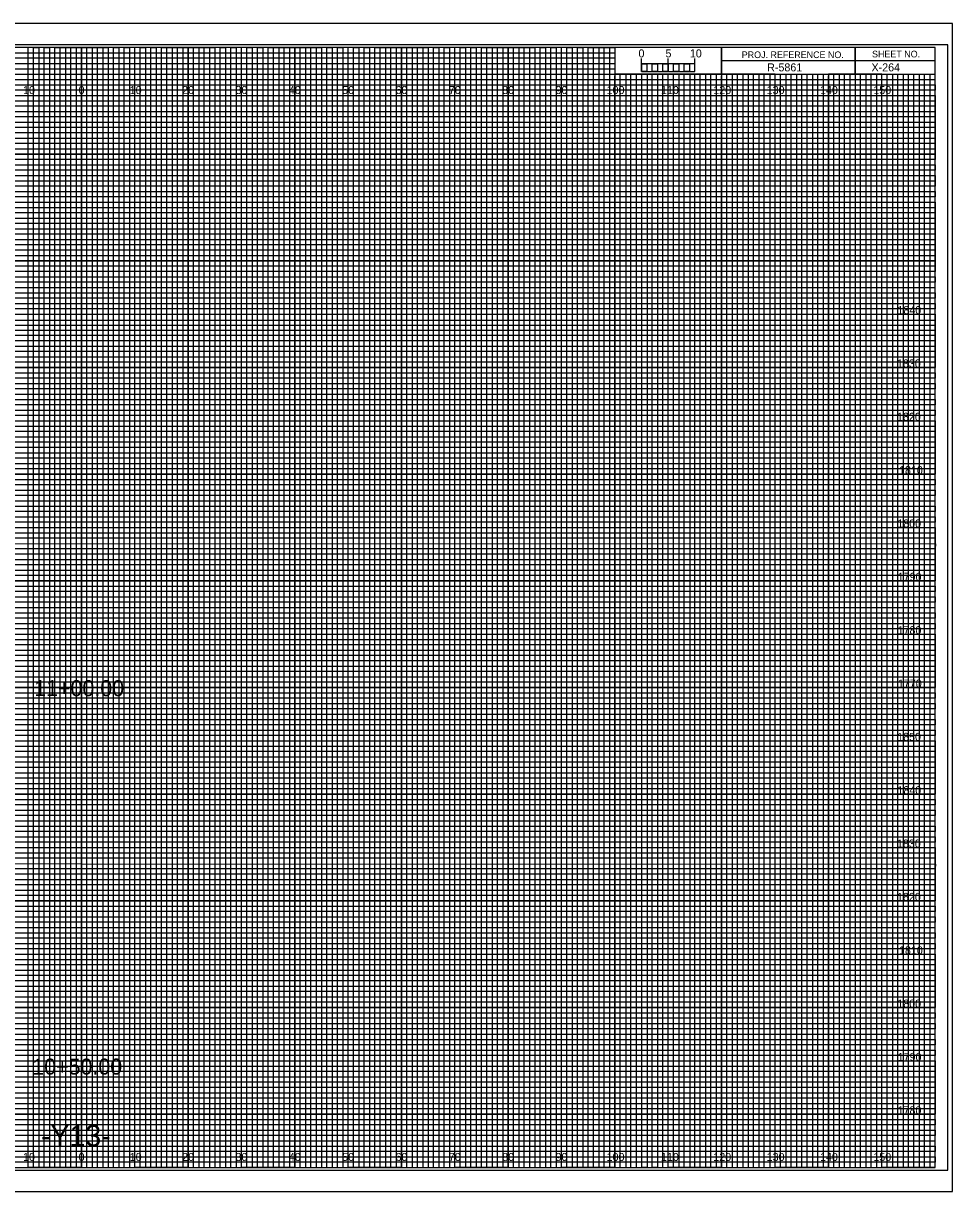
# Model space of a CAD drawing. Extents: x -13 to 323, y -5 to 654.
# Drawn here: x 149.1 to 323.3, y -4.5 to 214.5 of the extents above; entities that cross this region are included whole.
import ezdxf

# ---------------------------------------------------------------- set-up
doc = ezdxf.new("R2010")
doc.units = 0
for name, color, linetype in [('Prop Horizontal Alignment', 7, 'Continuous'), ('Prop XS Alignment Label', 7, 'Continuous'), ('Prop XS Bar Scale Labels', 7, 'Continuous'), ('Prop XS DDE', 7, 'Continuous'), ('Prop XS Earthwork Shape', 7, 'Continuous'), ('Prop XS Project Number', 7, 'Continuous'), ('Prop XS Sheet Number', 7, 'Continuous'), ('Raster_Level_0', 7, 'Continuous'), ('Scratch_Level_3', 7, 'Continuous'), ('Sheet Cross Section CELL', 7, 'Continuous'), ('Sheet Cross Section Grid Minor 1 CELL', 7, 'Continuous'), ('Sheet Cross Section Grid Minor 2 CELL', 7, 'Continuous'), ('Sheet Cross Section Scale CELL', 7, 'Continuous'), ('Sheet Cutting Line CELL', 7, 'Continuous'), ('Sheet DOT Grid CELL', 7, 'Continuous'), ('Sheet Plot Border Inside CELL', 7, 'Continuous'), ('Sheet Plot Border Outside CELL', 7, 'Continuous')]:
    doc.layers.add(name, color=color, linetype=linetype)

msp = doc.modelspace()

# ---------------------------------------------------------------- linework, layer by layer
at = {"layer": 'Prop XS DDE'}
for points in [[(145, 0), (155, 0), (155, 210), (165, 210), (165, 0), (175, 0), (175, 210), (185, 210), (185, 0), (195, 0), (195, 210), (205, 210), (205, 0), (215, 0), (215, 210), (225, 210), (225, 0), (235, 0), (235, 210), (245, 210), (245, 0), (255, 0), (255, 210), (259.93, 210), (260, 210), (260, 205), (264.99, 205), (264.99, 0), (275, 0), (275, 205), (285, 205), (285, 0), (295, 0), (295, 205), (305, 205), (305, 0), (315, 0), (315, 205)], [(0, 205), (275, 205)], [(0, 185), (320, 185), (320, 195), (0, 195)], [(0, 165), (320, 165), (320, 175), (0, 175)], [(0, 145), (320, 145), (320, 155), (0, 155)], [(0, 125), (320, 125), (320, 135), (0, 135)], [(0, 105), (320, 105), (320, 115), (0, 115)], [(0, 85), (320, 85), (320, 95), (0, 95)], [(0, 65), (320, 65), (320, 75), (0, 75)], [(0, 45), (320, 45), (320, 55), (0, 55)], [(0, 25), (320, 25), (320, 35), (0, 35)], [(0, 5), (320, 5), (320, 15), (0, 15)]]:
    msp.add_lwpolyline(points, dxfattribs=at)
at = {"layer": 'Prop XS Earthwork Shape'}
for p, q in [((150, 210), (140, 210)), ((150, 0), (150, 210)), ((170, 210), (160, 210)), ((160, 210), (160, 0)), ((170, 0), (170, 210)), ((190, 210), (180, 210)), ((180, 210), (180, 0)), ((190, 0), (190, 210)), ((210, 210), (200, 210)), ((200, 210), (200, 0)), ((210, 0), (210, 210)), ((230, 210), (220, 210)), ((220, 210), (220, 0)), ((230, 0), (230, 210)), ((250, 210), (240, 210)), ((240, 210), (240, 0)), ((250, 0), (250, 210)), ((260, 210), (260, 0)), ((270, 0), (270, 205)), ((290, 205), (280, 205)), ((280, 205), (280, 0)), ((290, 0), (290, 205)), ((310, 205), (300, 205)), ((300, 205), (300, 0)), ((310, 0), (310, 205)), ((160, 0), (150, 0)), ((180, 0), (170, 0)), ((200, 0), (190, 0)), ((220, 0), (210, 0)), ((240, 0), (230, 0)), ((260, 0), (250, 0)), ((280, 0), (270, 0)), ((300, 0), (290, 0)), ((320, 0), (310, 0)), ((320, 0), (320, 0))]:
    msp.add_line(p, q, dxfattribs=at)
for points in [[(0, 200), (320, 200), (320, 190), (0, 190)], [(0, 180), (320, 180), (320, 170), (0, 170)], [(0, 160), (320, 160), (320, 150), (0, 150)], [(0, 140), (320, 140), (320, 130), (0, 130)], [(0, 120), (320, 120), (320, 110), (0, 110)], [(0, 100), (320, 100), (320, 90), (0, 90)], [(0, 80), (320, 80), (320, 70), (0, 70)], [(0, 60), (320, 60), (320, 50), (0, 50)], [(0, 40), (320, 40), (320, 30), (0, 30)], [(0, 20), (320, 20), (320, 10), (0, 10)]]:
    msp.add_lwpolyline(points, dxfattribs=at)
at = {"layer": 'Sheet Cross Section CELL'}
for p, q in [((305, 210), (305, 205)), ((305, 205), (305, 210)), ((280, 207.5), (280, 205)), ((320, 207.49), (280, 207.49)), ((280, 205), (320, 205))]:
    msp.add_line(p, q, dxfattribs=at)
for points in [[(320, 210), (0, 210), (0, 0), (320, 0)], [(280, 210), (260, 210), (260, 205.03), (280, 205.03)], [(320, 210), (280, 210), (280, 205), (320, 205)]]:
    msp.add_lwpolyline(points, close=True, dxfattribs=at)
at = {"layer": 'Sheet Cross Section Grid Minor 1 CELL'}
for p, q in [((0, 209), (260, 209)), ((260, 209), (260, 207.98)), ((260, 207.98), (0, 207.98)), ((0, 207), (260, 207)), ((260, 205.89), (0, 205.89)), ((260, 207), (260, 205.89)), ((0, 204), (320, 204))]:
    msp.add_line(p, q, dxfattribs=at)
for points in [[(0, 203), (270, 203), (320, 203), (320, 202), (0, 202)], [(0, 201), (320, 201), (320, 199), (0, 199)], [(0, 198), (320, 198), (320, 197), (0, 196.98)], [(0, 196), (320, 196), (320, 194), (0, 194)], [(0, 193), (320, 193), (320, 192), (0, 192)], [(0, 191), (320, 191), (320, 189), (0, 189)], [(0, 188), (320, 188), (320, 187), (0, 187)], [(0, 186), (320, 186), (320, 184), (0, 184)], [(0, 183), (320, 183), (320, 182), (0, 182)], [(0, 181), (320, 181), (320, 179), (0, 179)], [(0, 178), (320, 178), (320, 177), (0, 177)], [(0, 176), (320, 176), (320, 173.95), (320, 173), (320, 172), (0, 172)], [(0, 174), (320, 174), (320, 173), (0, 173)], [(0, 171), (320, 171), (320, 169), (0, 169.03)], [(0, 169.03), (320, 169), (320, 168), (0, 168)], [(0, 167), (320, 167), (320, 166), (0, 166)], [(0, 164), (320, 164), (320, 163), (0, 163)], [(0, 162), (320, 162), (320, 161), (0, 161)], [(-0.07, 158.89), (320, 158.89), (320, 157.88), (-0.07, 157.88)], [(0, 157), (320, 157), (320, 156), (0, 156)], [(0, 154), (320, 154), (320, 153), (0, 153)], [(0, 152), (320, 152), (320, 151), (0, 151)], [(0, 149), (320, 149), (320, 148), (0, 148)], [(0, 147), (320, 147), (320, 146), (0, 146)], [(0, 144), (320, 144), (320, 143), (0, 143)], [(0, 142), (320, 142), (320, 141), (0, 141)], [(0, 139), (320, 139), (319.99, 137.98), (0, 138)], [(0, 137), (320, 137), (320, 136), (0, 136)], [(0, 134), (320, 134), (320, 133), (0, 133)], [(0, 132), (320, 132), (320, 131), (0, 131)], [(0, 129), (320, 129), (320, 128), (0, 128)], [(0, 127), (320, 127), (320, 126), (0, 126)], [(0, 124), (320, 124), (320, 123), (0, 123)], [(0, 122), (320, 122), (320, 121), (0, 121)], [(0, 119), (320, 119), (320, 118), (0, 118)], [(0, 116.99), (320.07, 116.91), (320, 116), (0, 116)], [(0, 114), (320, 114), (320, 113), (0, 113)], [(0, 112), (320, 112), (320, 111), (0, 111)], [(0, 109), (320, 109), (320, 108), (0, 108)], [(0, 107), (320, 107), (320, 106), (0, 106)], [(0, 104), (320, 104), (320, 103), (0, 103)], [(0, 102), (320, 102), (320, 101), (0, 101)], [(0, 99), (320, 99), (320, 98), (0, 98)], [(0, 97), (320, 97), (320, 96), (0, 96)], [(0, 94), (320, 94), (320, 93), (0, 93)], [(0, 92), (320, 92), (320, 91), (0, 91)], [(0, 89), (320, 89), (320, 88), (0, 88)], [(0, 87), (320, 87), (320, 86), (0, 86)], [(0, 84), (320, 84), (320, 83), (0, 83)], [(0, 82), (320, 82), (320, 81), (0, 81)], [(0, 79), (320, 79), (319.99, 77.98), (0, 78)], [(0, 77), (320, 77), (320, 76), (0, 76)], [(0, 74), (320, 74), (320, 73), (0, 73)], [(0, 72), (320, 72), (320, 71), (0, 71)], [(0, 69), (320, 69), (320, 68), (0, 68)], [(0, 67), (320, 67), (320, 66), (0, 66)], [(0, 64), (320, 64), (320, 63), (0, 63)], [(0, 62), (320, 62), (320, 61), (0, 61)], [(0, 59), (320, 59), (320, 58), (0, 58)], [(0, 56.99), (320.07, 56.91), (320, 56), (0, 56)], [(0, 54), (320, 54), (320, 53), (0, 53)], [(0, 52), (320, 52), (320, 51), (0, 51)], [(0, 49), (320, 49), (320, 48), (0, 48)], [(0, 47), (320, 47), (320, 46), (0, 46)], [(0, 44), (320, 44), (320, 43), (0, 43)], [(0, 42), (320, 42), (320, 41), (0, 41)], [(0, 39), (320, 39), (320, 38), (0, 38)], [(0, 37), (320, 37), (320, 36), (0, 36)], [(0, 34), (320, 34), (320, 33), (0, 33)], [(0, 32), (320, 32), (320, 31), (0, 31)], [(0, 29), (320, 29), (320, 28), (0, 28)], [(0, 27), (320, 27), (320, 26), (0, 26)], [(0, 24), (320, 24), (320, 23), (0, 23)], [(0, 22), (320, 22), (320, 21), (0, 21)], [(0, 19), (320, 19), (320, 18), (0, 18)], [(0, 17), (320, 17), (320, 16), (0, 16)], [(0, 14), (320, 14), (320, 13), (0, 13)], [(0, 12), (320, 12), (320, 11), (0, 11)], [(0, 9), (320, 9), (320, 8), (0, 8)], [(0, 7), (320, 7), (320, 6), (0, 6)], [(0, 4), (320, 4), (320, 3), (0, 3)], [(0, 2), (320, 2), (320, 1), (0, 1)]]:
    msp.add_lwpolyline(points, dxfattribs=at)
at = {"layer": 'Sheet Cross Section Grid Minor 2 CELL'}
for p, q in [((267, 205), (266.01, 205)), ((266.01, 205), (266.01, 0)), ((267, 0), (267, 205)), ((269, 205), (268, 205)), ((268, 205), (268, 0)), ((269, 0), (269, 205)), ((266.01, 0), (265, 0)), ((268, 0), (267, 0))]:
    msp.add_line(p, q, dxfattribs=at)
for points in [[(150, 0), (151, 0), (151, 210), (152, 210), (152, 0)], [(152, 0), (153, 0), (153, 210), (154, 210), (154, 0)], [(155, 0), (156, 0), (156, 210), (157, 210), (157, 0)], [(157, 0), (158, 0), (158, 210), (159, 210), (159, 0)], [(160, 0), (161, 0), (161, 210), (162, 210), (162, 0)], [(162, 0), (163, 0), (163, 210), (164, 210), (164, 0)], [(165, 0), (166, 0), (166, 210), (167, 210), (167, 0)], [(167, 0), (168, 0), (168, 210), (169, 210), (169, 0)], [(170, 0), (171, 0), (171, 210), (172, 210), (172, 0)], [(172, 0), (173, 0), (173, 210), (174, 210), (174, 0)], [(175, 0), (176, 0), (176, 210), (177, 210), (177, 0)], [(177, 0), (178, 0), (178, 210), (179, 210), (179, 0)], [(180, 0), (181, 0), (181, 210), (182, 210), (182, 0)], [(182, 0), (183, 0), (183, 210), (184, 210), (184, 0)], [(185, 0), (186, 0), (186, 210), (187, 210), (187, 0)], [(187, 0), (188, 0), (188, 210), (189, 210), (189, 0)], [(190, 0), (191, 0), (191, 210), (192, 210), (192, 0)], [(192, 0), (193, 0), (193, 210), (194, 210), (194, 0)], [(195, 0), (196, 0), (196, 210), (197, 210), (197, 0)], [(197, 0), (198, 0), (198, 210), (199, 210), (199, 0)], [(200, 0), (201, 0), (201, 210), (202, 210), (202, 0)], [(202, 0), (203, 0), (203, 210), (204, 210), (204, 0)], [(205, 0), (206, 0), (206, 210), (207, 210), (207, 0)], [(207, 0), (208, 0), (208, 210), (209, 210), (209, 0)], [(210, 0), (211, 0), (211, 210), (212, 210), (212, 0)], [(212, 0), (213, 0), (213, 210), (214, 210), (214, 0)], [(215, 0), (216, 0), (216, 210), (217, 210), (217, 0)], [(217, 0), (218, 0), (218, 210), (219, 210), (219, 0)], [(220, 0), (221, 0), (221, 210), (222, 210), (222, 0)], [(222, 0), (223, 0), (223, 210), (224, 210), (224, 0)], [(225, 0), (226, 0), (226, 210), (227, 210), (227, 0)], [(227, 0), (228, 0), (228, 210), (229, 210), (229, 0)], [(230, 0), (231, 0), (231, 210), (232, 210), (232, 0)], [(232, 0), (233, 0), (233, 210), (234, 210), (234, 0)], [(235, 0), (236, 0), (236, 210), (237, 210), (237, 0)], [(237, 0), (238, 0), (238, 210), (239, 210), (239, 0)], [(240, 0), (241, 0), (241, 210), (242, 210), (242, 0)], [(242, 0), (243, 0), (243, 210), (244, 210), (244, 0)], [(245, 0), (246, 0), (246, 210), (247, 210), (247, 0)], [(247, 0), (248, 0), (248, 210), (249, 210), (249, 0)], [(250, 0), (251, 0), (251, 210), (252, 210), (252, 0)], [(252, 0), (253, 0), (253, 210), (254, 210), (254, 0)], [(255, 0), (256, 0), (256, 210), (257, 210), (257, 0)], [(257, 0), (258, 0), (258, 210), (259, 210), (259, 0)], [(260, 0), (261, 0), (261, 205), (262.02, 205), (262.02, 0)], [(262, 0), (263, 0), (263, 205), (263.99, 205), (263.99, 0)], [(270, 0), (270.98, 0), (270.98, 205), (272, 205), (272, 0)], [(272, 0), (273, 0), (273, 205), (274.05, 205), (274.05, 0)], [(275, 0), (276, 0), (276, 205), (277, 205), (277, 0)], [(277, 0), (278, 0), (278, 205), (279, 205), (279, 0)], [(280, 0), (281, 0), (281, 205), (282, 205), (282, 0)], [(282, 0), (283, 0), (283, 205), (284, 205), (284, 0)], [(285, 0), (286, 0), (286, 205), (287, 205), (287, 0)], [(287, 0), (288, 0), (288, 205), (289, 205), (289, 0)], [(290, 0), (291, 0), (291, 205), (292, 205), (292, 0)], [(292, 0), (293, 0), (293, 205), (294, 205), (294, 0)], [(295, 0), (296, 0), (296, 205), (297, 205), (297, 0)], [(297, 0), (298, 0), (298, 205), (299, 205), (299, 0)], [(300, 0), (301, 0), (301, 205), (302, 205), (302, 0)], [(302, 0), (303, 0), (303, 205), (304, 205), (304, 0)], [(305, 0), (306, 0), (306, 205), (307, 205), (307, 0)], [(307, 0), (308, 0), (308, 205), (309, 205), (309, 0)], [(310, 0), (311, 0), (311, 205), (312, 205), (312, 0)], [(312, 0), (313, 0), (313, 205), (314, 205), (314, 0)], [(315, 0), (316, 0), (316, 205), (317, 205), (317, 0)], [(317, 0), (318, 0), (318, 205), (319, 205), (319, 0)]]:
    msp.add_lwpolyline(points, dxfattribs=at)
at = {"layer": 'Sheet Cross Section Scale CELL'}
for p, q in [((265, 205.49), (265, 207.9)), ((265, 206.9), (265, 207.9)), ((270, 205.49), (270, 207.9)), ((275, 205.49), (275, 207.9)), ((275, 206.9), (275, 207.9))]:
    msp.add_line(p, q, dxfattribs=at)
for points in [[(275, 206.9), (265, 206.9), (265, 205.49), (275, 205.49)], [(265, 206.9), (266, 206.9), (266, 205.49), (265, 205.49)], [(267, 206.9), (268, 206.9), (268, 205.49), (267, 205.49)], [(269, 206.9), (270, 206.9), (270, 205.49), (269, 205.49)], [(271, 206.9), (272, 206.9), (272, 205.49), (271, 205.49)], [(273, 206.9), (274, 206.9), (274, 205.49), (273, 205.49)]]:
    msp.add_lwpolyline(points, close=True, dxfattribs=at)
at = {"layer": 'Sheet Cutting Line CELL'}
for p, q in [((323.3, 214.5), (-13.4, 214.5)), ((-13.4, -4.5), (323.3, -4.5))]:
    msp.add_line(p, q, dxfattribs=at)
at = {"layer": 'Sheet DOT Grid CELL'}
for p, q in [((150, 0), (150, 210)), ((160, 0), (160, 210)), ((170, 0), (170, 210)), ((180, 0), (180, 210)), ((190, 0), (190, 210)), ((200, 0), (200, 210)), ((210, 0), (210, 210)), ((220, 0), (220, 210)), ((230, 0), (230, 210)), ((240, 0), (240, 210)), ((250, 0), (250, 210)), ((260, 0), (260, 204.69)), ((270, 0), (270, 204.69)), ((280, 0), (280, 204.69)), ((290, 0), (290, 204.69)), ((300, 0), (300, 204.69)), ((310, 0), (310, 204.69)), ((0, 200), (320, 200)), ((0, 190), (320, 190)), ((0, 180), (320, 180)), ((0, 170), (320, 170)), ((0, 160), (320, 160)), ((0, 150), (320, 150)), ((0, 140), (320, 140)), ((0, 130), (320, 130)), ((0, 120), (320, 120)), ((0, 110), (320, 110)), ((0, 100), (320, 100)), ((0, 90), (320, 90)), ((0, 80), (320, 80)), ((0, 70), (320, 70)), ((0, 60), (320, 60)), ((0, 50), (320, 50)), ((0, 40), (320, 40)), ((0, 30), (320, 30)), ((0, 20), (320, 20)), ((0, 10), (320, 10))]:
    msp.add_line(p, q, dxfattribs=at)
at = {"layer": 'Sheet Plot Border Inside CELL'}
msp.add_lwpolyline([(-10.8, -0.5), (322.4, -0.5), (322.4, 210.5), (-10.8, 210.5)], close=True, dxfattribs=at)
at = {"layer": 'Sheet Plot Border Outside CELL'}
msp.add_lwpolyline([(-13.4, -4.5), (323.3, -4.5), (323.3, 214.5), (-13.4, 214.5)], close=True, dxfattribs=at)

# ---------------------------------------------------------------- texts
at = {"layer": 'Prop Horizontal Alignment'}
for s, p in [('11+00.00', (151.13, 88.38)), ('10+50.00', (150.77, 17.44))]:
    msp.add_text(s, height=3, dxfattribs=at).set_placement(p)
at = {"layer": 'Prop XS Alignment Label'}
msp.add_text('-Y13-', height=4, dxfattribs=at).set_placement((152.39, 4))
at = {"layer": 'Prop XS Bar Scale Labels'}
for s, p in [('5', (269.47, 208.12)), ('10', (274.04, 208.12))]:
    msp.add_text(s, height=1.5, dxfattribs=at).set_placement(p)
at = {"layer": 'Prop XS Project Number'}
msp.add_text('R-5861', height=1.5, dxfattribs=at).set_placement((288.53, 205.5))
at = {"layer": 'Prop XS Sheet Number'}
msp.add_text('X-264', height=1.5, dxfattribs=at).set_placement((308.09, 205.5))
at = {"layer": 'Raster_Level_0'}
for s, p in [('10', (149.04, 201.25)), ('0', (159.45, 201.25)), ('0', (159.45, 201.25)), ('10', (169.04, 201.25)), ('20', (178.86, 201.25)), ('30', (188.86, 201.25)), ('40', (198.86, 201.25)), ('50', (208.86, 201.25)), ('60', (218.86, 201.25)), ('70', (228.86, 201.25)), ('80', (238.86, 201.25)), ('90', (248.86, 201.25)), ('100', (258.44, 201.25)), ('110', (268.62, 201.25)), ('120', (278.44, 201.25)), ('130', (288.44, 201.25)), ('140', (298.44, 201.25)), ('150', (308.44, 201.25)), ('10', (149.04, 1.25)), ('0', (159.45, 1.25)), ('0', (159.45, 1.25)), ('10', (169.04, 1.25)), ('20', (178.86, 1.25)), ('30', (188.86, 1.25)), ('40', (198.86, 1.25)), ('50', (208.86, 1.25)), ('60', (218.86, 1.25)), ('70', (228.86, 1.25)), ('80', (238.86, 1.25)), ('90', (248.86, 1.25)), ('100', (258.44, 1.25)), ('110', (268.62, 1.25)), ('120', (278.44, 1.25)), ('130', (288.44, 1.25)), ('140', (298.44, 1.25)), ('150', (308.44, 1.25))]:
    msp.add_text(s, height=1.5, dxfattribs=at).set_placement(p)
at = {"layer": 'Scratch_Level_3'}
for s, p in [('1840', (312.95, 160)), ('1830', (312.86, 150)), ('1820', (312.87, 140)), ('1810', (313.25, 130)), ('1800', (312.92, 120)), ('1790', (313, 110)), ('1780', (312.98, 100)), ('1770', (313.04, 90)), ('1850', (312.9, 80)), ('1840', (312.95, 70)), ('1830', (312.86, 60)), ('1820', (312.87, 50)), ('1810', (313.25, 40)), ('1800', (312.92, 30)), ('1790', (313, 20)), ('1780', (312.98, 10))]:
    msp.add_text(s, height=1.5, dxfattribs=at).set_placement(p)
at = {"layer": 'Sheet Cross Section CELL'}
for s, p in [('PROJ. REFERENCE NO.', (283.77, 207.99)), ('SHEET NO.', (308.19, 208.12))]:
    msp.add_text(s, height=1.25, dxfattribs=at).set_placement(p)
at = {"layer": 'Sheet Cross Section Scale CELL'}
msp.add_text('0', height=1.5, dxfattribs=at).set_placement((264.41, 208.12))

doc.saveas('drawing.dxf')
